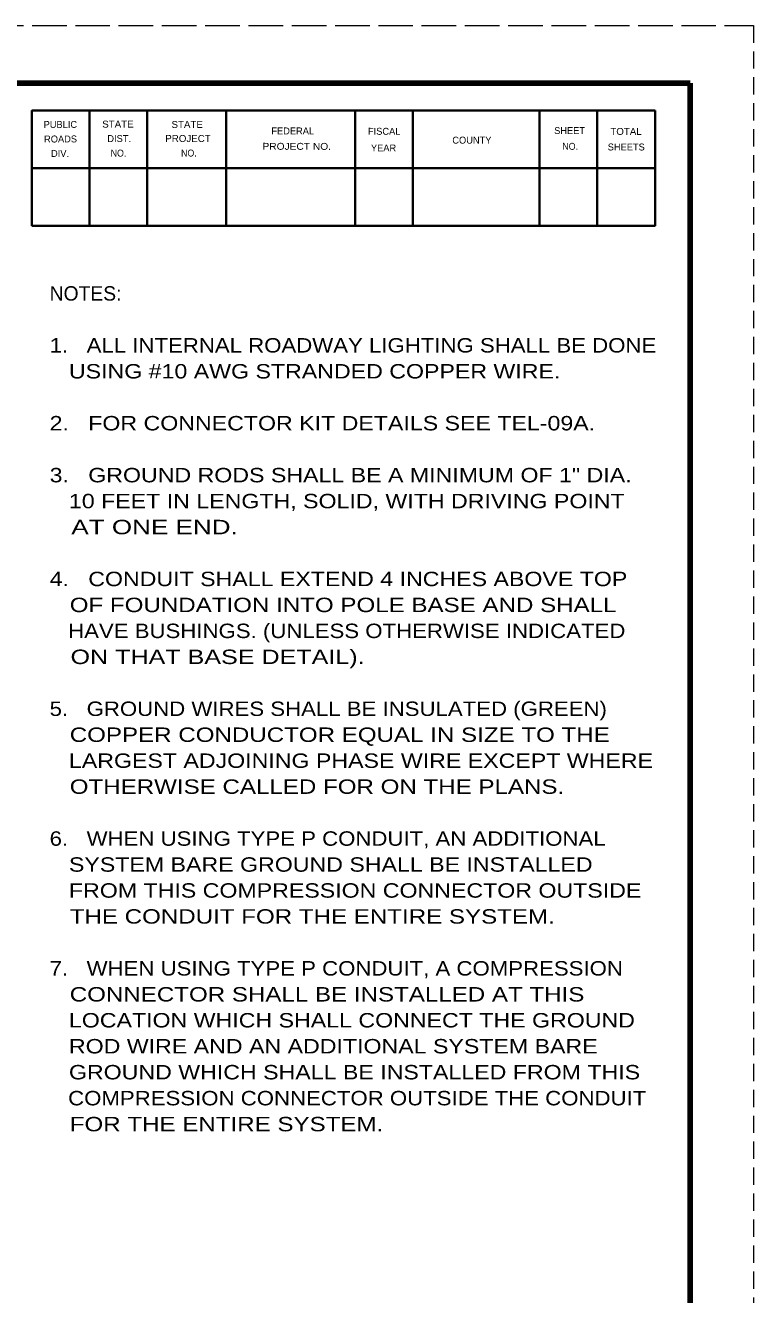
# Model space of a CAD drawing. Extents: x -153 to 527, y -247 to 194.
# Drawn here: x 400.8 to 527, y -26.5 to 193.5 of the extents above; entities that cross this region are included whole.
import ezdxf

# ---------------------------------------------------------------- set-up
doc = ezdxf.new("R2010")
doc.units = 0
doc.linetypes.add('LONG_DASHED', pattern=[7.5, 6, -1.5])
doc.linetypes.add('MEDIUM_DASHED', pattern=[4.5, 3, -1.5])
doc.layers.add('1', color=7, linetype='Continuous', lineweight=53)
doc.layers.add('61', color=7, linetype='Continuous', lineweight=35)

msp = doc.modelspace()

# ---------------------------------------------------------------- linework, layer by layer
at = {"layer": '1', "linetype": 'MEDIUM_DASHED', "lineweight": 13}
msp.add_line((526.958, 193.509), (526.938, -246.511), dxfattribs=at)
at = {"layer": '61', "linetype": 'LONG_DASHED', "lineweight": 13}
msp.add_line((-153.062, 193.509), (526.958, 193.509), dxfattribs=at)
at = {"layer": '61', "lineweight": 158}
msp.add_line((515.978, 183.509), (515.998, -236.531), dxfattribs=at)
at = {"layer": '61'}
for p, q in [((411.898, 178.749), (411.898, 158.749)), ((421.898, 178.749), (421.898, 158.749)), ((435.578, 178.749), (435.578, 158.749)), ((457.898, 178.749), (457.898, 158.749)), ((467.898, 178.749), (467.898, 158.749)), ((489.878, 178.769), (489.878, 158.769)), ((499.878, 178.769), (499.878, 158.769)), ((509.898, 168.729), (401.878, 168.749))]:
    msp.add_line(p, q, dxfattribs=at)
at = {"layer": '61', "lineweight": 158}
msp.add_lwpolyline([(515.978, 183.509), (-123.062, 183.509), (-123.062, -236.511)], dxfattribs=at)
at = {"layer": '61'}
for points in [[(509.878, 178.769), (401.898, 178.749), (401.898, 158.749)], [(509.878, 178.769), (509.878, 158.769), (401.898, 158.749)]]:
    msp.add_lwpolyline(points, dxfattribs=at)

# ---------------------------------------------------------------- texts
at = {"layer": '1'}
msp.add_text('NOTES:', height=2.5, dxfattribs=at).set_placement((404.982, 145.798))
for s, width, p in [('1.   ALL INTERNAL ROADWAY LIGHTING SHALL BE DONE', 1.15, (404.982, 136.798)), ('   USING #10 AWG STRANDED COPPER WIRE.', 1.2, (404.982, 132.298)), ('2.   FOR CONNECTOR KIT DETAILS SEE TEL-09A.', 1.2, (404.982, 123.298)), ('3.   GROUND RODS SHALL BE A MINIMUM OF 1" DIA.', 1.2, (404.982, 114.298)), ('   10 FEET IN LENGTH, SOLID, WITH DRIVING POINT', 1.2, (404.982, 109.798)), ('   AT ONE END.', 1.35, (404.982, 105.298)), ('4.   CONDUIT SHALL EXTEND 4 INCHES ABOVE TOP', 1.2, (404.982, 96.298)), ('   OF FOUNDATION INTO POLE BASE AND SHALL', 1.25, (404.982, 91.798)), ('   HAVE BUSHINGS. (UNLESS OTHERWISE INDICATED', 1.15, (404.982, 87.298)), ('   ON THAT BASE DETAIL).', 1.3, (404.982, 82.798)), ('5.   GROUND WIRES SHALL BE INSULATED (GREEN)', 1.15, (404.982, 73.798)), ('   COPPER CONDUCTOR EQUAL IN SIZE TO THE', 1.25, (404.982, 69.298)), ('   LARGEST ADJOINING PHASE WIRE EXCEPT WHERE', 1.2, (404.982, 64.798)), ('   OTHERWISE CALLED FOR ON THE PLANS.', 1.25, (404.982, 60.298)), ('6.   WHEN USING TYPE P CONDUIT, AN ADDITIONAL', 1.15, (404.982, 51.298)), ('   SYSTEM BARE GROUND SHALL BE INSTALLED', 1.2, (404.982, 46.798)), ('   FROM THIS COMPRESSION CONNECTOR OUTSIDE', 1.2, (404.982, 42.298)), ('   THE CONDUIT FOR THE ENTIRE SYSTEM.', 1.25, (404.982, 37.798)), ('7.   WHEN USING TYPE P CONDUIT, A COMPRESSION', 1.15, (404.982, 28.798)), ('   CONNECTOR SHALL BE INSTALLED AT THIS', 1.25, (404.982, 24.298)), ('   LOCATION WHICH SHALL CONNECT THE GROUND', 1.2, (404.982, 19.798)), ('   ROD WIRE AND AN ADDITIONAL SYSTEM BARE', 1.2, (404.982, 15.298)), ('   GROUND WHICH SHALL BE INSTALLED FROM THIS', 1.2, (404.982, 10.798)), ('   COMPRESSION CONNECTOR OUTSIDE THE CONDUIT', 1.15, (404.982, 6.298)), ('   FOR THE ENTIRE SYSTEM.', 1.25, (404.982, 1.798))]:
    msp.add_text(s, height=2.5, dxfattribs=dict(at, width=width)).set_placement(p)
at = {"layer": '61'}
for s, rotation, p in [('PUBLIC', 0.033, (403.938, 175.729)), ('ROADS', 0.124, (404.018, 173.209)), ('DIST.', 0.056, (414.978, 173.289)), ('FEDERAL', 0.007, (443.398, 174.609)), ('FISCAL', 359.942, (460.138, 174.549)), ('COUNTY', 0.069, (474.758, 173.009)), ('SHEET', 0.059, (492.398, 174.669)), ('DIV.', 359.932, (405.218, 170.709)), ('YEAR', 0.105, (460.658, 171.649)), ('SHEETS', 359.959, (501.678, 171.829))]:
    msp.add_text(s, height=1.201, rotation=rotation, dxfattribs=at).set_placement(p)
for s, rotation, width, p in [('STATE', 0.059, 1.05, (414.098, 175.789)), ('STATE', 0.059, 1.05, (426.098, 175.729)), ('PROJECT', 359.908, 1.05, (425.018, 173.309)), ('TOTAL', 359.926, 1.05, (502.138, 174.529)), ('NO.', 359.852, 0.95, (415.558, 170.769)), ('NO.', 0.225, 0.95, (427.758, 170.769)), ('PROJECT NO.', 359.922, 1.1, (441.858, 171.949)), ('NO.', 359.852, 0.95, (493.818, 171.949))]:
    msp.add_text(s, height=1.201, rotation=rotation, dxfattribs=dict(at, width=width)).set_placement(p)

doc.saveas('drawing.dxf')
